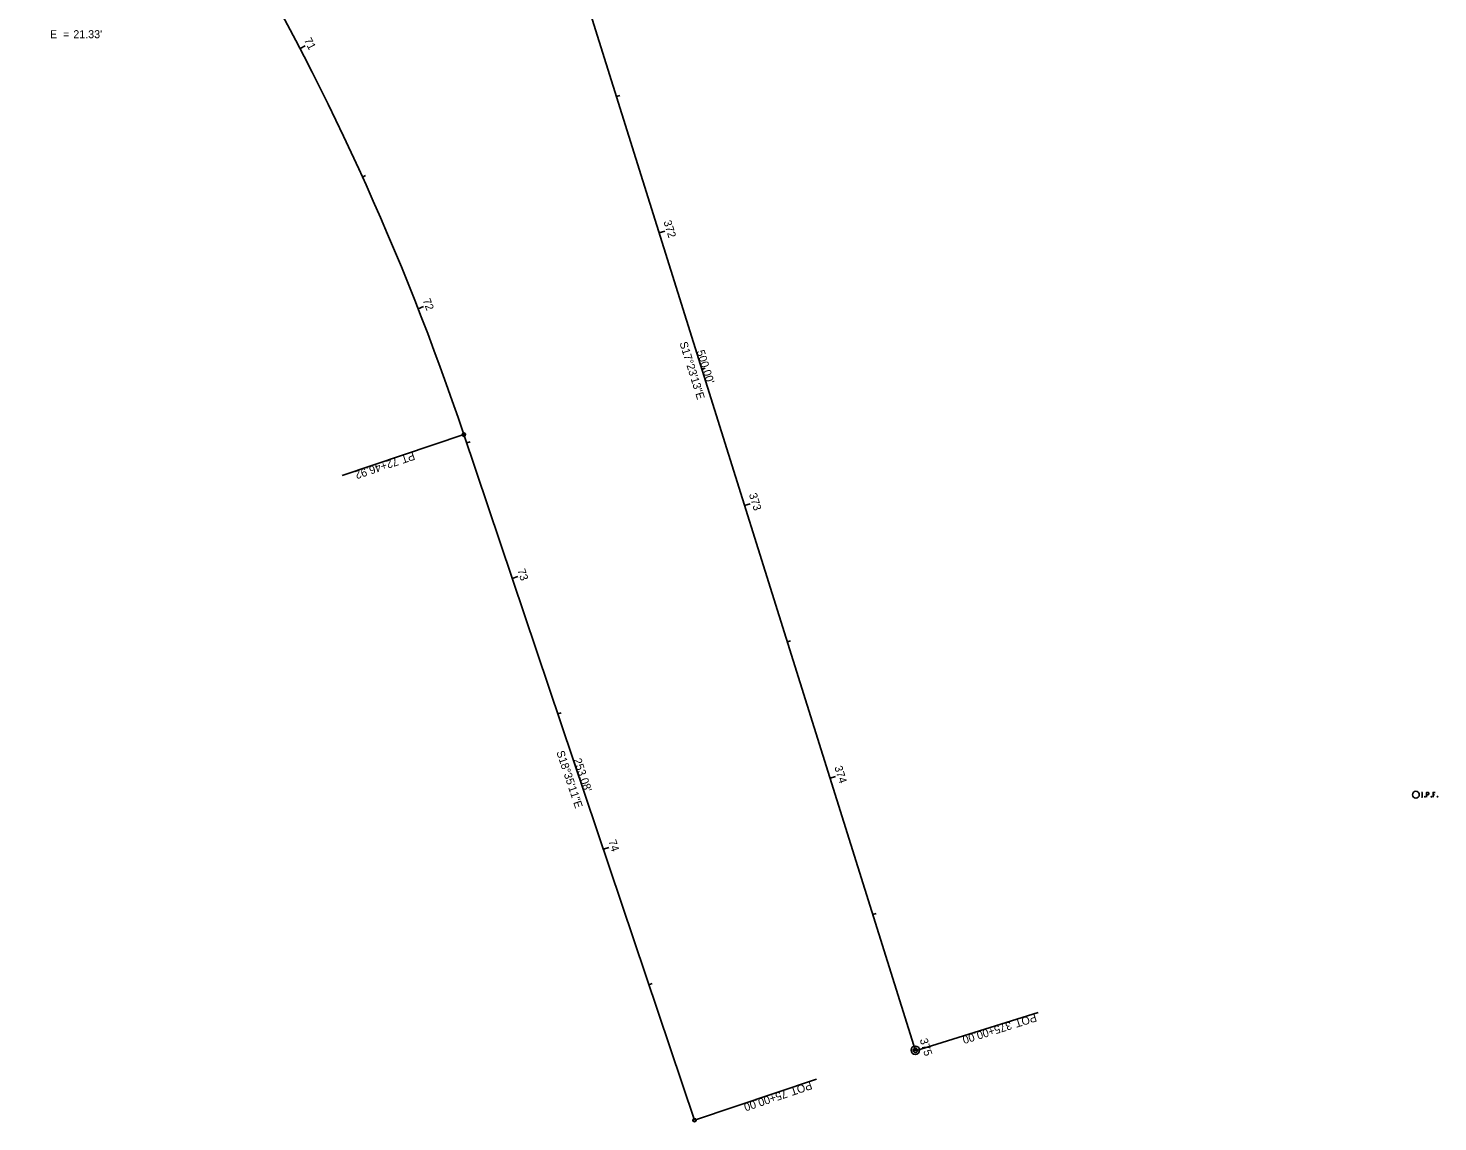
# Model space of a CAD drawing. Extents: x 1918148 to 1920349, y 624677 to 627727.
# Drawn here: x 1919304 to 1919797.2, y 624677.5 to 625060.2 of the extents above; entities that cross this region are included whole.
import ezdxf

# ---------------------------------------------------------------- set-up
doc = ezdxf.new("R2010")
doc.units = 0
for name, color, linetype in [('_CIVIL_CONSTRUCTION', 7, 'Continuous'), ('RS_Raster1', 7, 'Continuous'), ('RW_X_CL', 7, 'Continuous'), ('RW_X_CL_100_Bearings', 7, 'Continuous'), ('RW_X_CL_100_Cardinal_Points', 7, 'Continuous'), ('RW_X_CL_100_Curve_Data', 7, 'Continuous'), ('SV_X_Mon_Cells_Found', 7, 'Continuous')]:
    doc.layers.add(name, color=color, linetype=linetype)

msp = doc.modelspace()

# ---------------------------------------------------------------- linework, layer by layer
at = {"layer": 'RS_Raster1'}
for p, q in [((1919465, 625179.46), (1919614.42, 624702.31)), ((1919456.43, 624917.95), (1919537.1, 624678.07))]:
    msp.add_line(p, q, dxfattribs=at)
msp.add_arc((1918551.3, 624613.58), 954.93, 18.58639, 42.58667, dxfattribs=at)
at = {"layer": 'RW_X_CL'}
for p, q in [((1919456.43, 624917.95), (1919413.78, 624903.61)), ((1919614.42, 624702.31), (1919657.36, 624715.75)), ((1919537.1, 624678.07), (1919579.75, 624692.41))]:
    msp.add_line(p, q, dxfattribs=at)
for centre in [(1919456.43, 624917.95), (1919614.42, 624702.31), (1919537.1, 624678.07)]:
    msp.add_circle(centre, 0.6, dxfattribs=at)
at = {"layer": 'RW_X_CL_100_Cardinal_Points'}
for p, q in [((1919399.1, 625053.06), (1919400.87, 625053.98)), ((1919509.83, 625036.31), (1919510.97, 625036.67)), ((1919420.94, 625008.09), (1919422.03, 625008.58)), ((1919524.77, 624988.6), (1919526.68, 624989.2)), ((1919440.39, 624962.03), (1919442.25, 624962.76)), ((1919539.71, 624940.88), (1919540.85, 624941.24)), ((1919457.42, 624915.03), (1919458.55, 624915.41)), ((1919554.65, 624893.17), (1919556.56, 624893.76)), ((1919473.35, 624867.64), (1919475.25, 624868.27)), ((1919569.59, 624845.45), (1919570.74, 624845.81)), ((1919489.29, 624820.24), (1919490.43, 624820.63)), ((1919584.53, 624797.74), (1919586.44, 624798.33)), ((1919505.23, 624772.85), (1919507.12, 624773.49)), ((1919599.47, 624750.02), (1919600.62, 624750.38)), ((1919521.16, 624725.46), (1919522.3, 624725.84)), ((1919614.42, 624702.31), (1919616.32, 624702.9))]:
    msp.add_line(p, q, dxfattribs=at)
at = {"layer": 'SV_X_Mon_Cells_Found'}
for points in [[(1919791.53, 624792.73), (1919791.88, 624792.73)], [(1919791.7, 624791.13), (1919791.7, 624792.73)], [(1919793.27, 624791.13), (1919793.27, 624792.73), (1919793.8, 624792.73), (1919793.85, 624792.71), (1919793.93, 624792.69), (1919793.96, 624792.66), (1919794, 624792.64), (1919794.04, 624792.58), (1919794.07, 624792.51), (1919794.1, 624792.41), (1919794.1, 624792.26), (1919794.08, 624792.21), (1919794.06, 624792.13), (1919794.02, 624792.05), (1919793.97, 624792.01), (1919793.94, 624791.98), (1919793.89, 624791.96), (1919793.8, 624791.95), (1919793.27, 624791.95)], [(1919796.28, 624792.73), (1919795.52, 624792.73), (1919795.52, 624791.13)], [(1919791.53, 624791.13), (1919791.88, 624791.13)], [(1919792.66, 624791.34), (1919792.72, 624791.34), (1919792.75, 624791.32), (1919792.78, 624791.27), (1919792.78, 624791.2), (1919792.75, 624791.15), (1919792.72, 624791.13), (1919792.66, 624791.13), (1919792.63, 624791.15), (1919792.6, 624791.2), (1919792.6, 624791.27), (1919792.63, 624791.32), (1919792.66, 624791.34)], [(1919794.91, 624791.34), (1919794.97, 624791.34), (1919795, 624791.32), (1919795.03, 624791.27), (1919795.03, 624791.2), (1919795, 624791.15), (1919794.97, 624791.13), (1919794.91, 624791.13), (1919794.88, 624791.15), (1919794.85, 624791.2), (1919794.85, 624791.27), (1919794.88, 624791.32), (1919794.91, 624791.34)], [(1919795.52, 624791.95), (1919796.06, 624791.95)], [(1919797.06, 624791.34), (1919797.12, 624791.34), (1919797.15, 624791.32), (1919797.18, 624791.27), (1919797.18, 624791.2), (1919797.15, 624791.15), (1919797.12, 624791.13), (1919797.06, 624791.13), (1919797.03, 624791.15), (1919796.99, 624791.2), (1919796.99, 624791.27), (1919797.03, 624791.32), (1919797.06, 624791.34)]]:
    msp.add_lwpolyline(points, dxfattribs=at)
for centre, radius in [((1919789.51, 624791.93), 1.2), ((1919614.36, 624702.5), 1.5), ((1919614.36, 624702.5), 0.8)]:
    msp.add_circle(centre, radius, dxfattribs=at)

# ---------------------------------------------------------------- texts
at = {"layer": '_CIVIL_CONSTRUCTION'}
for s, rotation, p in [('S17°23\'13"E', 287.387, (1919531.82, 624950.02)), ('S18°35\'11"E', 288.5864, (1919488.73, 624806.84))]:
    msp.add_text(s, height=2.8, rotation=rotation, dxfattribs=at).set_placement(p)
at = {"layer": 'RW_X_CL'}
for s, rotation, p in [('PT', 198.5864, (1919438.69, 624911.93)), ('72+46.92', 198.5864, (1919432.92, 624909.99)), ('POT', 197.387, (1919656.3, 624715.37)), ('375+00.00', 197.387, (1919647.59, 624712.64)), ('POT', 198.5864, (1919577.67, 624691.66)), ('75+00.00', 198.5864, (1919569.02, 624688.75))]:
    msp.add_text(s, height=2.8, rotation=rotation, dxfattribs=at).set_placement(p)
at = {"layer": 'RW_X_CL_100_Bearings'}
for s, p in [('E  = ', (1919311.59, 625056.68)), ("21.33'", (1919319.75, 625056.68))]:
    msp.add_text(s, height=2.8, dxfattribs=at).set_placement(p)
at = {"layer": 'RW_X_CL_100_Cardinal_Points'}
for s, rotation, p in [('71', 297.4013, (1919400.39, 625056.01)), ('372', 287.387, (1919526.22, 624992.48)), ('72', 291.4013, (1919441.92, 624964.98)), ('373', 287.387, (1919556.11, 624897.04)), ('73', 288.5864, (1919475.07, 624870.51)), ('374', 287.387, (1919586, 624801.59)), ('74', 288.5864, (1919506.91, 624775.69)), ('375', 287.387, (1919615.86, 624706.21))]:
    msp.add_text(s, height=2.8, rotation=rotation, dxfattribs=at).set_placement(p)
at = {"layer": 'RW_X_CL_100_Curve_Data'}
for s, rotation, p in [("500.00'", 287.387, (1919537.82, 624947.09)), ("253.08'", 288.5864, (1919494.74, 624804.17))]:
    msp.add_text(s, height=2.8, rotation=rotation, dxfattribs=at).set_placement(p)

doc.saveas('drawing.dxf')
